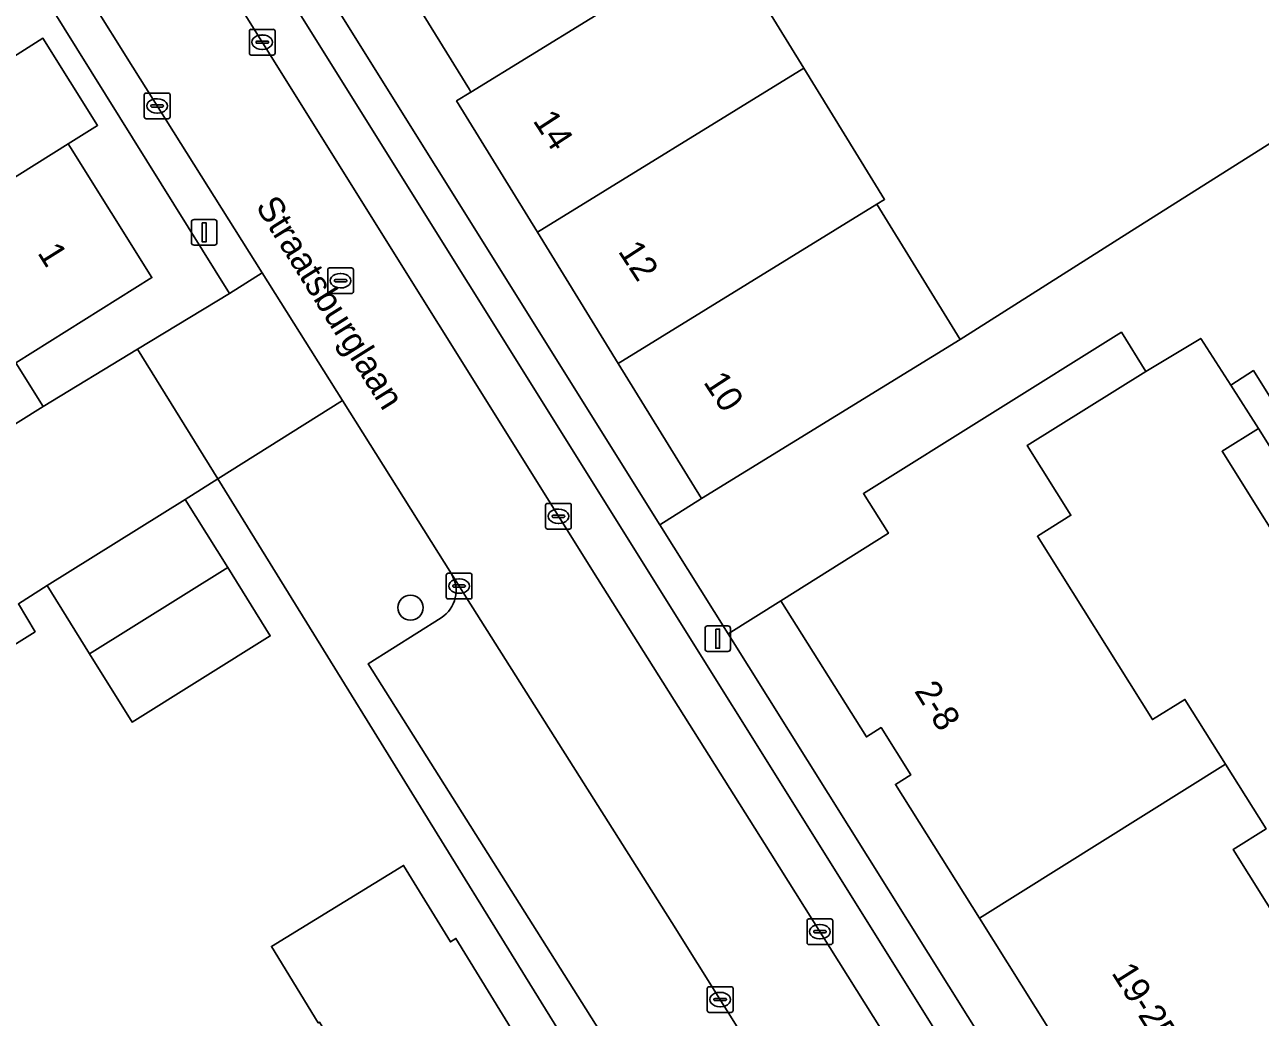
# Model space of a CAD drawing. Extents: x 157767 to 159172, y 387839 to 389425.
# Drawn here: x 158744.91 to 158792.99, y 388191.62 to 388230.25 of the extents above; entities that cross this region are included whole.
import ezdxf

# ---------------------------------------------------------------- set-up
doc = ezdxf.new("R2010")
doc.units = 0
for name, color, linetype in [('IMGEO_Boom', 7, 'Continuous'), ('IMGEO_Erf', 7, 'Continuous'), ('IMGEO_Kolk', 7, 'Continuous'), ('IMGEO_Lichtmast', 7, 'Continuous'), ('IMGEO_Muur', 7, 'Continuous'), ('IMGEO_Openbare_ruimte_label', 7, 'Continuous'), ('IMGEO_Pand', 7, 'Continuous'), ('IMGEO_Pand_nummerreeks', 7, 'Continuous'), ('IMGEO_Parkeervlak_open', 7, 'Continuous'), ('IMGEO_Rijbaan_lokaal_open', 7, 'Continuous'), ('IMGEO_Rioolput', 7, 'Continuous'), ('IMGEO_Voetpad_open', 7, 'Continuous')]:
    doc.layers.add(name, color=color, linetype=linetype)

msp = doc.modelspace()

# ---------------------------------------------------------------- linework, layer by layer
at = {"layer": 'IMGEO_Boom'}
msp.add_circle((158759.923, 388207.564), 0.489, dxfattribs=at)
at = {"layer": 'IMGEO_Erf'}
for points in [[(158734.05, 388250), (158732.567, 388252.38), (158728.101, 388249.597), (158731.365, 388244.39), (158734.487, 388239.411), (158734.552, 388239.307), (158737.031, 388240.859), (158740.219, 388235.775), (158743.406, 388230.692), (158744.466, 388229.002), (158745.619, 388229.725), (158747.747, 388226.331), (158746.599, 388225.612), (158746.689, 388225.469), (158749.859, 388220.412), (158744.564, 388217.093), (158745.627, 388215.399), (158749.297, 388217.622), (158752.874, 388219.788)], [(158764.86, 388222.178), (158761.714, 388227.289), (158762.272, 388227.632), (158762.214, 388227.726), (158759.126, 388232.741), (158758.108, 388234.394), (158756.883, 388233.64), (158754.664, 388237.243), (158758.156, 388239.394), (158756.798, 388241.6), (158752.185, 388238.694), (158769.629, 388210.79), (158771.243, 388211.81), (158768.005, 388217.07)]]:
    msp.add_lwpolyline(points, close=True, dxfattribs=at)
for points in [[(158772.141, 388233.581), (158775.23, 388228.563), (158778.375, 388223.455), (158778.07, 388223.267), (158781.309, 388218.006), (158787.986, 388222.228), (158794.745, 388226.501)], [(158799.586, 388167.503), (158811.429, 388174.954), (158815.858, 388177.741), (158811.5, 388184.707), (158810.03, 388183.785), (158806.679, 388189.13), (158808.15, 388190.052), (158803.865, 388197.034), (158802.451, 388196.151), (158799.096, 388201.525), (158800.51, 388202.408), (158796.279, 388209.161), (158794.865, 388208.278), (158791.51, 388213.652), (158792.924, 388214.535), (158791.842, 388216.226), (158790.68, 388218.041), (158788.543, 388216.76), (158783.927, 388213.879), (158785.624, 388211.162), (158784.322, 388210.346), (158788.799, 388203.206), (158790.058, 388203.995)], [(158768.796, 388186.091), (158764.571, 388192.927), (158755.721, 388207.244), (158752.421, 388212.583), (158751.155, 388211.778), (158752.808, 388209.125), (158754.466, 388206.462), (158749.088, 388203.113), (158747.432, 388205.772), (158745.777, 388208.429), (158744.664, 388207.707), (158745.313, 388206.627), (158741.321, 388204.133), (158738.293, 388202.241), (158740.903, 388198.051), (158738.693, 388196.675), (158733.513, 388193.45), (158730.902, 388197.632), (158728.127, 388195.948), (158730.775, 388191.695), (158728.443, 388190.242)], [(158785.331, 388190.257), (158782.061, 388195.472), (158778.794, 388200.683), (158779.39, 388201.057), (158778.239, 388202.893), (158777.665, 388202.532), (158774.34, 388207.835), (158772.284, 388206.543), (158783.962, 388187.903)], [(158790.058, 388203.995), (158791.638, 388201.474), (158793.218, 388198.953), (158791.939, 388198.151), (158796.404, 388191.03), (158797.67, 388191.824), (158799.282, 388189.252)], [(158756.335, 388191.4), (158754.508, 388194.376), (158759.652, 388197.534), (158761.479, 388194.557), (158761.692, 388194.688), (158765.881, 388187.864)]]:
    msp.add_lwpolyline(points, dxfattribs=at)
at = {"layer": 'IMGEO_Kolk'}
for p, q in [((158753.651, 388229.147), (158753.651, 388229.999)), ((158753.726, 388230.073), (158754.578, 388230.073)), ((158754.139, 388229.853), (158754.164, 388229.853)), ((158754.652, 388229.999), (158754.652, 388229.147)), ((158753.91, 388229.567), (158753.91, 388229.579)), ((158754.348, 388229.53), (158753.95, 388229.53)), ((158753.953, 388229.616), (158754.351, 388229.616)), ((158754.394, 388229.579), (158754.394, 388229.567)), ((158754.578, 388229.073), (158753.726, 388229.073)), ((158754.162, 388229.293), (158754.137, 388229.293)), ((158749.562, 388226.666), (158749.562, 388227.518)), ((158749.637, 388227.592), (158750.489, 388227.592)), ((158750.563, 388227.518), (158750.563, 388226.666)), ((158749.821, 388227.086), (158749.821, 388227.098)), ((158750.259, 388227.049), (158749.861, 388227.049)), ((158749.864, 388227.135), (158750.262, 388227.135)), ((158750.05, 388227.372), (158750.075, 388227.372)), ((158750.305, 388227.098), (158750.305, 388227.086)), ((158750.489, 388226.592), (158749.637, 388226.592)), ((158750.073, 388226.812), (158750.048, 388226.812)), ((158765.18, 388210.695), (158765.18, 388211.547)), ((158765.255, 388211.621), (158766.107, 388211.621)), ((158766.181, 388211.547), (158766.181, 388210.695)), ((158765.439, 388211.115), (158765.439, 388211.127)), ((158765.877, 388211.078), (158765.479, 388211.078)), ((158765.482, 388211.164), (158765.88, 388211.164)), ((158765.668, 388211.401), (158765.693, 388211.401)), ((158765.923, 388211.127), (158765.923, 388211.115)), ((158766.107, 388210.621), (158765.255, 388210.621)), ((158765.691, 388210.841), (158765.666, 388210.841)), ((158761.314, 388207.977), (158761.314, 388208.829)), ((158761.389, 388208.903), (158762.241, 388208.903)), ((158761.802, 388208.683), (158761.827, 388208.683)), ((158762.315, 388208.829), (158762.315, 388207.977)), ((158761.573, 388208.397), (158761.573, 388208.409)), ((158762.011, 388208.36), (158761.613, 388208.36)), ((158761.616, 388208.446), (158762.014, 388208.446)), ((158762.057, 388208.409), (158762.057, 388208.397)), ((158762.241, 388207.903), (158761.389, 388207.903)), ((158761.825, 388208.123), (158761.8, 388208.123)), ((158775.355, 388194.525), (158775.355, 388195.377)), ((158775.43, 388195.451), (158776.282, 388195.451)), ((158775.843, 388195.231), (158775.868, 388195.231)), ((158776.356, 388195.377), (158776.356, 388194.525)), ((158775.614, 388194.945), (158775.614, 388194.957)), ((158776.052, 388194.908), (158775.654, 388194.908)), ((158775.657, 388194.994), (158776.055, 388194.994)), ((158776.098, 388194.957), (158776.098, 388194.945)), ((158776.282, 388194.451), (158775.43, 388194.451)), ((158775.866, 388194.671), (158775.841, 388194.671)), ((158771.548, 388192.811), (158772.4, 388192.811)), ((158771.473, 388191.885), (158771.473, 388192.737)), ((158771.732, 388192.305), (158771.732, 388192.317)), ((158771.775, 388192.354), (158772.173, 388192.354)), ((158771.961, 388192.591), (158771.986, 388192.591)), ((158772.216, 388192.317), (158772.216, 388192.305)), ((158772.474, 388192.737), (158772.474, 388191.885)), ((158772.4, 388191.811), (158771.548, 388191.811)), ((158772.17, 388192.268), (158771.772, 388192.268)), ((158771.984, 388192.031), (158771.959, 388192.031))]:
    msp.add_line(p, q, dxfattribs=at)
for points in [[(158753.651, 388229.147), (158753.651, 388229.999)], [(158753.726, 388230.073), (158754.578, 388230.073)], [(158754.652, 388229.999), (158754.652, 388229.147)], [(158754.578, 388229.073), (158753.726, 388229.073)], [(158749.562, 388226.666), (158749.562, 388227.518)], [(158749.637, 388227.592), (158750.489, 388227.592)], [(158750.563, 388227.518), (158750.563, 388226.666)], [(158750.489, 388226.592), (158749.637, 388226.592)], [(158765.18, 388210.695), (158765.18, 388211.547)], [(158765.255, 388211.621), (158766.107, 388211.621)], [(158766.181, 388211.547), (158766.181, 388210.695)], [(158766.107, 388210.621), (158765.255, 388210.621)], [(158761.314, 388207.977), (158761.314, 388208.829)], [(158761.389, 388208.903), (158762.241, 388208.903)], [(158762.315, 388208.829), (158762.315, 388207.977)], [(158762.241, 388207.903), (158761.389, 388207.903)], [(158775.355, 388194.525), (158775.355, 388195.377)], [(158775.43, 388195.451), (158776.282, 388195.451)], [(158776.356, 388195.377), (158776.356, 388194.525)], [(158776.282, 388194.451), (158775.43, 388194.451)], [(158771.548, 388192.811), (158772.4, 388192.811)], [(158771.473, 388191.885), (158771.473, 388192.737)], [(158772.474, 388192.737), (158772.474, 388191.885)], [(158772.4, 388191.811), (158771.548, 388191.811)]]:
    msp.add_lwpolyline(points, dxfattribs=at)
for centre, radius, start, end in [((158753.728, 388229.997), 0.0765, 91.552, 178.448), ((158753.728, 388229.997), 0.0765, 91.552, 178.448), ((158754.576, 388229.997), 0.0765, 1.552, 88.448), ((158754.576, 388229.997), 0.0765, 1.552, 88.448), ((158753.95, 388229.576), 0.0403, 85.8775, 175.7526), ((158753.947, 388229.566), 0.0366, 178.938, 274.7102), ((158754.351, 388229.573), 0.043, 264.8664, 352.4533), ((158754.355, 388229.578), 0.0386, 1.7309, 96.639), ((158753.728, 388229.149), 0.0765, 181.552, 268.448), ((158753.728, 388229.149), 0.0765, 181.552, 268.448), ((158754.576, 388229.149), 0.0765, 271.552, 358.448), ((158754.576, 388229.149), 0.0765, 271.552, 358.448), ((158749.639, 388227.516), 0.0765, 91.552, 178.448), ((158749.639, 388227.516), 0.0765, 91.552, 178.448), ((158750.487, 388227.516), 0.0765, 1.552, 88.448), ((158750.487, 388227.516), 0.0765, 1.552, 88.448), ((158749.861, 388227.095), 0.0403, 85.8775, 175.7526), ((158749.858, 388227.085), 0.0366, 178.938, 274.7102), ((158750.262, 388227.092), 0.043, 264.8664, 352.4533), ((158750.266, 388227.097), 0.0386, 1.7309, 96.639), ((158749.639, 388226.668), 0.0765, 181.552, 268.448), ((158749.639, 388226.668), 0.0765, 181.552, 268.448), ((158750.487, 388226.668), 0.0765, 271.552, 358.448), ((158750.487, 388226.668), 0.0765, 271.552, 358.448), ((158765.257, 388211.545), 0.0765, 91.552, 178.448), ((158765.257, 388211.545), 0.0765, 91.552, 178.448), ((158766.105, 388211.545), 0.0765, 1.552, 88.448), ((158766.105, 388211.545), 0.0765, 1.552, 88.448), ((158765.479, 388211.124), 0.0403, 85.8775, 175.7526), ((158765.476, 388211.114), 0.0366, 178.938, 274.7102), ((158765.88, 388211.121), 0.043, 264.8664, 352.4533), ((158765.884, 388211.126), 0.0386, 1.7309, 96.639), ((158765.257, 388210.697), 0.0765, 181.552, 268.448), ((158765.257, 388210.697), 0.0765, 181.552, 268.448), ((158766.105, 388210.697), 0.0765, 271.552, 358.448), ((158766.105, 388210.697), 0.0765, 271.552, 358.448), ((158761.391, 388208.827), 0.0765, 91.552, 178.448), ((158761.391, 388208.827), 0.0765, 91.552, 178.448), ((158762.239, 388208.827), 0.0765, 1.552, 88.448), ((158762.239, 388208.827), 0.0765, 1.552, 88.448), ((158761.613, 388208.406), 0.0403, 85.8775, 175.7526), ((158761.61, 388208.396), 0.0366, 178.938, 274.7102), ((158762.014, 388208.403), 0.043, 264.8664, 352.4533), ((158762.018, 388208.408), 0.0386, 1.7309, 96.639), ((158761.391, 388207.979), 0.0765, 181.552, 268.448), ((158761.391, 388207.979), 0.0765, 181.552, 268.448), ((158762.239, 388207.979), 0.0765, 271.552, 358.448), ((158762.239, 388207.979), 0.0765, 271.552, 358.448), ((158775.432, 388195.375), 0.0765, 91.552, 178.448), ((158775.432, 388195.375), 0.0765, 91.552, 178.448), ((158776.28, 388195.375), 0.0765, 1.552, 88.448), ((158776.28, 388195.375), 0.0765, 1.552, 88.448), ((158775.654, 388194.954), 0.0403, 85.8775, 175.7526), ((158775.651, 388194.944), 0.0366, 178.938, 274.7102), ((158776.055, 388194.951), 0.043, 264.8664, 352.4533), ((158776.059, 388194.956), 0.0386, 1.7309, 96.639), ((158775.432, 388194.527), 0.0765, 181.552, 268.448), ((158775.432, 388194.527), 0.0765, 181.552, 268.448), ((158776.28, 388194.527), 0.0765, 271.552, 358.448), ((158776.28, 388194.527), 0.0765, 271.552, 358.448), ((158771.55, 388192.735), 0.0765, 91.552, 178.448), ((158771.55, 388192.735), 0.0765, 91.552, 178.448), ((158772.398, 388192.735), 0.0765, 1.552, 88.448), ((158772.398, 388192.735), 0.0765, 1.552, 88.448), ((158771.772, 388192.314), 0.0403, 85.8775, 175.7526), ((158771.769, 388192.304), 0.0366, 178.938, 274.7102), ((158772.173, 388192.311), 0.043, 264.8664, 352.4533), ((158772.177, 388192.316), 0.0386, 1.7309, 96.639), ((158771.55, 388191.887), 0.0765, 181.552, 268.448), ((158771.55, 388191.887), 0.0765, 181.552, 268.448), ((158772.398, 388191.887), 0.0765, 271.552, 358.448), ((158772.398, 388191.887), 0.0765, 271.552, 358.448)]:
    msp.add_arc(centre, radius, start, end, dxfattribs=at)
for centre, major_axis, ratio, start_param, end_param in [((158754.138, 388229.573), (-0.387, 0.002), 0.722429, 4.712389, 7.853982), ((158754.163, 388229.573), (-0.39, 0.002), 0.717154, 1.570796, 4.712389), ((158750.049, 388227.092), (-0.387, 0.002), 0.722429, 4.712389, 7.853982), ((158750.074, 388227.092), (-0.39, 0.002), 0.717154, 1.570796, 4.712389), ((158765.667, 388211.121), (-0.387, 0.002), 0.722429, 4.712389, 7.853982), ((158765.692, 388211.121), (-0.39, 0.002), 0.717154, 1.570796, 4.712389), ((158761.801, 388208.403), (-0.387, 0.002), 0.722429, 4.712389, 7.853982), ((158761.826, 388208.403), (-0.39, 0.002), 0.717154, 1.570796, 4.712389), ((158775.842, 388194.951), (-0.387, 0.002), 0.722429, 4.712389, 7.853982), ((158775.867, 388194.951), (-0.39, 0.002), 0.717154, 1.570796, 4.712389), ((158771.96, 388192.311), (-0.387, 0.002), 0.722429, 4.712389, 7.853982), ((158771.985, 388192.311), (-0.39, 0.002), 0.717154, 1.570796, 4.712389)]:
    msp.add_ellipse(centre, major_axis=major_axis, ratio=ratio, start_param=start_param, end_param=end_param, dxfattribs=at)
at = {"layer": 'IMGEO_Lichtmast'}
for p, q in [((158751.398, 388221.772), (158751.398, 388222.572)), ((158751.398, 388222.572), (158751.398, 388221.772)), ((158751.498, 388222.672), (158752.288, 388222.672)), ((158752.288, 388222.672), (158751.498, 388222.672)), ((158752.388, 388222.572), (158752.388, 388221.772)), ((158752.388, 388221.772), (158752.388, 388222.572)), ((158752.288, 388221.672), (158751.498, 388221.672)), ((158751.498, 388221.672), (158752.288, 388221.672)), ((158771.384, 388205.957), (158771.384, 388206.757)), ((158771.384, 388206.757), (158771.384, 388205.957)), ((158771.484, 388206.857), (158772.274, 388206.857)), ((158772.274, 388206.857), (158771.484, 388206.857)), ((158772.374, 388206.757), (158772.374, 388205.957)), ((158772.374, 388205.957), (158772.374, 388206.757)), ((158772.274, 388205.857), (158771.484, 388205.857)), ((158771.484, 388205.857), (158772.274, 388205.857))]:
    msp.add_line(p, q, dxfattribs=at)
for points in [[(158751.818, 388222.547), (158751.968, 388222.547), (158751.968, 388221.797), (158751.818, 388221.797), (158751.818, 388222.547)], [(158771.804, 388206.732), (158771.954, 388206.732), (158771.954, 388205.982), (158771.804, 388205.982), (158771.804, 388206.732)]]:
    msp.add_lwpolyline(points, dxfattribs=at)
for centre, start, end in [((158751.498, 388222.572), 90, 180), ((158751.498, 388222.572), 90, 180), ((158752.288, 388222.572), 0, 90), ((158752.288, 388222.572), 360, 90), ((158751.498, 388221.772), 180, 270), ((158751.498, 388221.772), 180, 270), ((158752.288, 388221.772), 270, 0), ((158752.288, 388221.772), 270, 0), ((158771.484, 388206.757), 90, 180), ((158771.484, 388206.757), 90, 180), ((158772.274, 388206.757), 0, 90), ((158772.274, 388206.757), 360, 90), ((158771.484, 388205.957), 180, 270), ((158771.484, 388205.957), 180, 270), ((158772.274, 388205.957), 270, 0), ((158772.274, 388205.957), 270, 0)]:
    msp.add_arc(centre, 0.1, start, end, dxfattribs=at)
at = {"layer": 'IMGEO_Muur'}
for points in [[(158781.309, 388218.006), (158787.986, 388222.228)], [(158788.543, 388216.76), (158790.68, 388218.041), (158791.842, 388216.226)], [(158791.842, 388216.226), (158792.924, 388214.535)], [(158755.721, 388207.244), (158764.571, 388192.927)]]:
    msp.add_lwpolyline(points, dxfattribs=at)
at = {"layer": 'IMGEO_Pand'}
for points in [[(158769.234, 388231.919), (158766.088, 388237.028), (158759.126, 388232.741), (158762.214, 388227.726), (158762.272, 388227.632)], [(158772.141, 388233.581), (158769.291, 388231.826), (158769.234, 388231.919), (158762.272, 388227.632), (158761.714, 388227.289), (158764.86, 388222.178), (158775.23, 388228.563)], [(158745.619, 388229.725), (158744.466, 388229.002), (158743.406, 388230.692), (158736.425, 388226.321), (158739.616, 388221.24), (158746.599, 388225.612), (158747.747, 388226.331)], [(158775.23, 388228.563), (158764.86, 388222.178), (158768.005, 388217.07), (158778.07, 388223.267), (158778.375, 388223.455)], [(158749.859, 388220.412), (158746.689, 388225.469), (158746.599, 388225.612), (158739.616, 388221.24), (158741.967, 388217.495), (158739.433, 388215.906), (158741.408, 388212.754), (158745.627, 388215.399), (158744.564, 388217.093)], [(158768.005, 388217.07), (158771.243, 388211.81), (158778.249, 388216.123), (158781.309, 388218.006), (158778.07, 388223.267)], [(158782.061, 388195.472), (158791.638, 388201.474), (158790.058, 388203.995), (158788.799, 388203.206), (158784.322, 388210.346), (158785.624, 388211.162), (158783.927, 388213.879), (158788.543, 388216.76), (158787.592, 388218.284), (158777.551, 388212.005), (158778.522, 388210.457), (158774.34, 388207.835), (158777.665, 388202.532), (158778.239, 388202.893), (158779.39, 388201.057), (158778.794, 388200.683)], [(158796.279, 388209.161), (158792.924, 388214.535), (158791.51, 388213.652), (158794.865, 388208.278)], [(158752.808, 388209.125), (158751.155, 388211.778), (158745.777, 388208.429), (158747.432, 388205.772)], [(158752.808, 388209.125), (158747.432, 388205.772), (158749.088, 388203.113), (158754.466, 388206.462)], [(158799.282, 388189.252), (158797.67, 388191.824), (158796.404, 388191.03), (158791.939, 388198.151), (158793.218, 388198.953), (158791.638, 388201.474), (158782.061, 388195.472), (158785.331, 388190.257), (158785.916, 388190.624), (158786.995, 388188.903), (158786.443, 388188.557), (158789.753, 388183.278)], [(158761.692, 388194.688), (158761.479, 388194.557), (158759.652, 388197.534), (158754.508, 388194.376), (158756.335, 388191.4), (158756.383, 388191.43), (158760.624, 388184.637), (158765.881, 388187.864)]]:
    msp.add_lwpolyline(points, close=True, dxfattribs=at)
at = {"layer": 'IMGEO_Parkeervlak_open'}
msp.add_lwpolyline([(158781.298, 388186.286), (158782.775, 388187.209), (158751.892, 388236.644), (158751.388, 388236.331), (158750.346, 388235.683), (158754.82, 388228.502), (158767.195, 388208.702), (158773.917, 388198.04)], close=True, dxfattribs=at)
for points in [[(158774.093, 388188.923), (158770.088, 388195.314), (158762.101, 388207.947), (158761.515, 388208.878)], [(158761.115, 388207.173), (158758.272, 388205.375), (158769.711, 388187.241), (158772.782, 388189.182)]]:
    msp.add_lwpolyline(points, dxfattribs=at)
msp.add_arc((158760.448, 388208.229), 1.249, 302.2798, 31.3141, dxfattribs=at)
at = {"layer": 'IMGEO_Rijbaan_lokaal_open'}
for points in [[(158781.651, 388185.725), (158781.298, 388186.286), (158773.917, 388198.04), (158767.195, 388208.702), (158754.82, 388228.502), (158750.346, 388235.683), (158749.699, 388236.721), (158747, 388241.052), (158741.436, 388250), (158729.583, 388268.931), (158723.372, 388278.281), (158717.582, 388283.848), (158716.063, 388284.997), (158711.707, 388279.239), (158714.205, 388276.844), (158715.334, 388275.761), (158716.781, 388277.271), (158726.034, 388268.399), (158724.583, 388266.886)], [(158727.22, 388263.567), (158735.718, 388250), (158749.112, 388228.601), (158754.146, 388220.596), (158757.271, 388215.627), (158761.515, 388208.878), (158762.101, 388207.947), (158770.088, 388195.314), (158774.093, 388188.923)], [(158794.745, 388226.501), (158787.986, 388222.228), (158781.309, 388218.006), (158778.249, 388216.123), (158771.243, 388211.81), (158769.629, 388210.79), (158772.284, 388206.543), (158774.34, 388207.835), (158778.522, 388210.457), (158777.551, 388212.005), (158787.592, 388218.284), (158788.543, 388216.76), (158790.68, 388218.041), (158791.842, 388216.226), (158792.727, 388216.793), (158816.757, 388178.304)], [(158741.321, 388204.133), (158745.313, 388206.627), (158744.664, 388207.707), (158745.777, 388208.429), (158751.155, 388211.778), (158752.421, 388212.583), (158749.297, 388217.622), (158745.627, 388215.399), (158741.408, 388212.754)]]:
    msp.add_lwpolyline(points, dxfattribs=at)
at = {"layer": 'IMGEO_Rioolput'}
for p, q in [((158756.701, 388219.863), (158756.701, 388220.715)), ((158756.776, 388220.789), (158757.628, 388220.789)), ((158757.702, 388220.715), (158757.702, 388219.863)), ((158756.96, 388220.283), (158756.96, 388220.295)), ((158757.398, 388220.246), (158757, 388220.246)), ((158757.003, 388220.332), (158757.401, 388220.332)), ((158757.189, 388220.569), (158757.214, 388220.569)), ((158757.444, 388220.295), (158757.444, 388220.283)), ((158757.628, 388219.789), (158756.776, 388219.789)), ((158757.212, 388220.009), (158757.187, 388220.009))]:
    msp.add_line(p, q, dxfattribs=at)
for points in [[(158756.701, 388219.863), (158756.701, 388220.715)], [(158756.776, 388220.789), (158757.628, 388220.789)], [(158757.702, 388220.715), (158757.702, 388219.863)], [(158757.628, 388219.789), (158756.776, 388219.789)]]:
    msp.add_lwpolyline(points, dxfattribs=at)
for centre, radius, start, end in [((158756.778, 388220.713), 0.0765, 91.552, 178.448), ((158756.778, 388220.713), 0.0765, 91.552, 178.448), ((158757.626, 388220.713), 0.0765, 1.552, 88.448), ((158757.626, 388220.713), 0.0765, 1.552, 88.448), ((158757, 388220.292), 0.0403, 85.8775, 175.7526), ((158756.997, 388220.282), 0.0366, 178.938, 274.7102), ((158757.401, 388220.289), 0.043, 264.8664, 352.4533), ((158757.405, 388220.294), 0.0386, 1.7309, 96.639), ((158756.778, 388219.865), 0.0765, 181.552, 268.448), ((158756.778, 388219.865), 0.0765, 181.552, 268.448), ((158757.626, 388219.865), 0.0765, 271.552, 358.448), ((158757.626, 388219.865), 0.0765, 271.552, 358.448)]:
    msp.add_arc(centre, radius, start, end, dxfattribs=at)
for centre, major_axis, ratio, start_param, end_param in [((158757.188, 388220.289), (-0.387, 0.002), 0.722429, 4.712389, 7.853982), ((158757.213, 388220.289), (-0.39, 0.002), 0.717154, 1.570796, 4.712389)]:
    msp.add_ellipse(centre, major_axis=major_axis, ratio=ratio, start_param=start_param, end_param=end_param, dxfattribs=at)
at = {"layer": 'IMGEO_Voetpad_open'}
for points in [[(158783.962, 388187.903), (158772.284, 388206.543), (158769.629, 388210.79), (158752.185, 388238.694), (158749.551, 388242.908), (158747.498, 388241.623), (158743.908, 388247.396), (158739.118, 388255.018), (158737.42, 388257.733), (158731.197, 388267.839), (158754.633, 388282.527), (158753.914, 388283.586), (158751.704, 388282.231), (158747.13, 388279.426), (158742.93, 388276.824), (158737.745, 388281.958), (158741.126, 388285.372), (158735.926, 388290.522)], [(158723.372, 388278.281), (158729.583, 388268.931), (158741.436, 388250), (158747, 388241.052), (158749.699, 388236.721), (158750.346, 388235.683), (158751.388, 388236.331), (158751.892, 388236.644), (158782.775, 388187.209), (158781.298, 388186.286), (158781.651, 388185.725)], [(158724.583, 388266.886), (158715.334, 388275.761), (158714.205, 388276.844), (158712.975, 388276.074), (158725.17, 388264.253), (158731.744, 388253.702), (158732.567, 388252.38), (158734.05, 388250), (158752.874, 388219.788), (158754.146, 388220.596), (158749.112, 388228.601), (158735.718, 388250)], [(158757.271, 388215.627), (158752.421, 388212.583), (158755.721, 388207.244), (158764.571, 388192.927), (158768.796, 388186.091), (158769.711, 388187.241), (158758.272, 388205.375), (158761.115, 388207.173)], [(158761.515, 388208.878), (158757.271, 388215.627)]]:
    msp.add_lwpolyline(points, dxfattribs=at)
for points in [[(158754.146, 388220.596), (158752.874, 388219.788), (158749.297, 388217.622), (158752.421, 388212.583), (158757.271, 388215.627)], [(158792.727, 388216.793), (158791.842, 388216.226), (158792.924, 388214.535), (158796.279, 388209.161), (158800.51, 388202.408), (158803.865, 388197.034), (158808.15, 388190.052), (158811.5, 388184.707), (158815.858, 388177.741), (158816.757, 388178.304)]]:
    msp.add_lwpolyline(points, close=True, dxfattribs=at)
msp.add_arc((158760.448, 388208.229), 1.249, 302.2798, 31.3141, dxfattribs=at)

# ---------------------------------------------------------------- texts
at = {"layer": 'IMGEO_Openbare_ruimte_label'}
msp.add_text('Straatsburglaan', height=1, rotation=302.0054, dxfattribs=at).set_placement((158753.873, 388223.185))
at = {"layer": 'IMGEO_Pand_nummerreeks'}
for s, rotation, p in [('14', 303.0996, (158764.663, 388226.518)), ('1', 302.1026, (158745.383, 388221.375)), ('12', 303.0991, (158767.978, 388221.435)), ('10', 303.0991, (158771.297, 388216.343)), ('2-8', 301.9858, (158779.507, 388204.32)), ('19-25', 302.0861, (158787.181, 388193.351))]:
    msp.add_text(s, height=1, rotation=rotation, dxfattribs=at).set_placement(p)

doc.saveas('drawing.dxf')
